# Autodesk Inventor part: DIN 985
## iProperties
SaveDate: 2002-10-25
SaveTime: 10:34
TotalMass: 0.0 kg
TotalVolume: 0.0 mm^3
Author: Cor de Vlaming
Shininess: 64.0
Angle Display Precision: 2
Document Length Units: 11269
Document Angle Units: 11283
Document Time Units: 11279
Document Mass Units: 11290
Document Length Units Precision: 3
Document Angle Units Precision: 2
Compacted: True
PropertySet Name: _Private Model Information
Created: 2002-09
Part Number: DIN 985
Cost Center: 0.0 kg
Material: Steel, Mild
Description: Mutter DIN 985
Document SubType Name: Modeling
Designer: Cor de Vlaming
Engineer: Cor de Vlaming
Authority: 0.0 mm^3
Control State: 0
Master: False
Checked Out: False
PropertySet Name: Design Tracking Control
Density: 0.0
Volumn: 0.0
Area: 0.0
PropertySet Name: Model Information
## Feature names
1. Extrusion1
2. Revolution1
3. Mirror1
4. Extrusion3
5. Chamfer2
6. Extrusion6
7. Revolution2
